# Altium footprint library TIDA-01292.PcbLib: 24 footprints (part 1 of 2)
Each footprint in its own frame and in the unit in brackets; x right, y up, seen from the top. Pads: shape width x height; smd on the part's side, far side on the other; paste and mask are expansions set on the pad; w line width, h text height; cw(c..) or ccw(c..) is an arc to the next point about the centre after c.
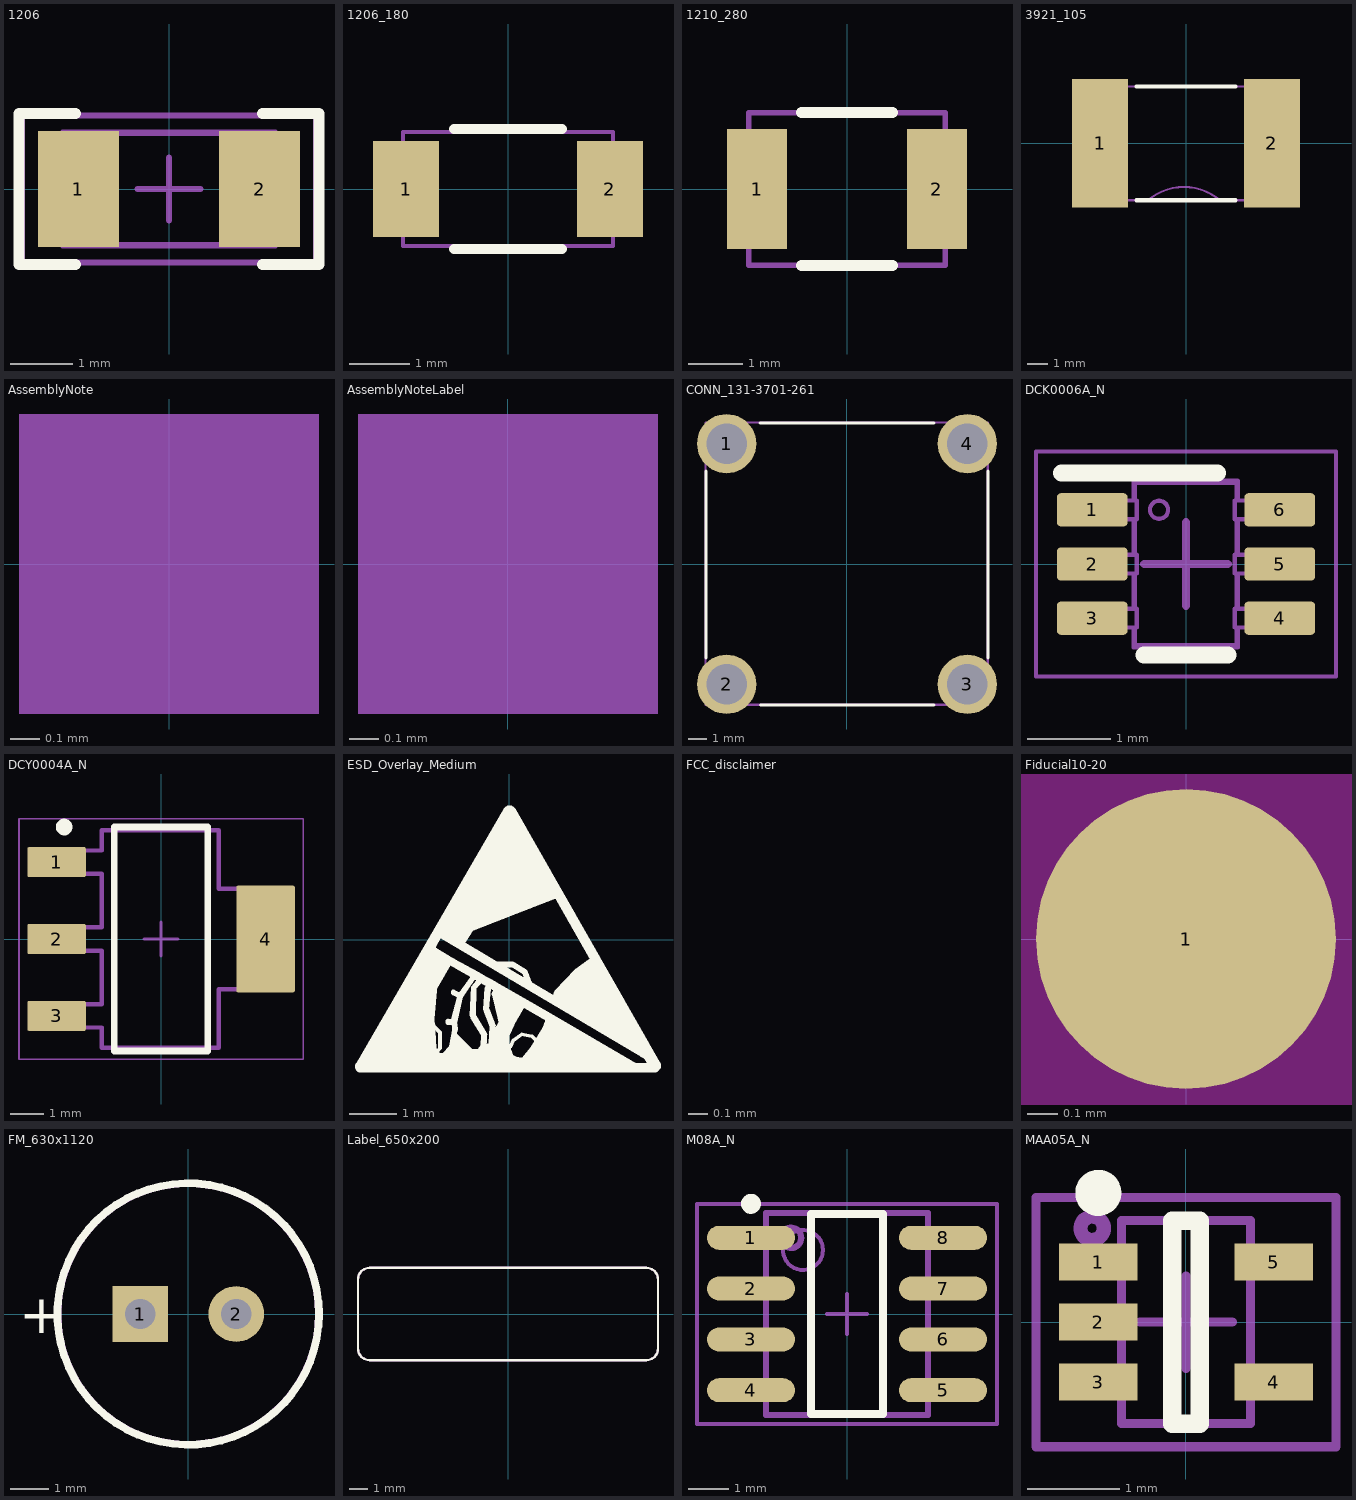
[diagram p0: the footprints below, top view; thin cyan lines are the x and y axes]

## 1206 [mm] "1206 from SM-752 data"
height 1.35
pads (2):
  rect 1.3x1.85 smd: 1(-1.45,0) 2(1.45,0)
Top Overlay:
  lines w0.178: -1.5,-1.21 -2.4,-1.21 -2.4,1.21 -1.5,1.21 ; 1.5,-1.21 2.4,-1.21 2.4,1.21 1.5,1.21
Mechanical 5:
  lines w0.1: -1.7,-0.9 -1.7,0.9 1.7,0.9 1.7,-0.9 -1.7,-0.9
  text ".Designator" at -1.475,-0.4 h0.89
Mechanical 13:
  lines w0.1: -1.2,-0.9 -1.2,0.9 ; 1.2,-0.9 1.2,0.9 ; -1.7,-0.9 -1.7,0.9 1.7,0.9 1.7,-0.9 -1.7,-0.9
Mechanical 15:
  lines w0.1: -0.5,0 0.5,0 ; 0,-0.5 0,0.5 ; -2.35,-1.175 -2.35,1.175 2.35,1.175 2.35,-1.175 -2.35,-1.175
3D body: height 1.35, standoff 0, extent 1.201,-0.899 1.699,0.899
3D body: height 1.35, standoff 0, extent -1.199,-0.899 1.199,0.899
3D body: height 1.35, standoff 0, extent -1.699,-0.899 -1.201,0.899

## 1206_180 [mm] "1206_180"
height 1.8
pads (2):
  rect 1.1x1.6 smd: 1(-1.7,0) 2(1.7,0)
Top Overlay:
  lines w0.17: -0.9,-1 0.9,-1 ; -0.9,1 0.9,1
Mechanical 5:
  lines w0.07: -1.75,-0.95 1.75,-0.95 1.75,0.95 -1.75,0.95 -1.75,-0.95
  text ".Designator" at 1.143,0.432 h0.89
3D body: height 1.8, standoff 0, extent -1.241,-0.949 -0.793,0.949
3D body: height 1.8, standoff 0, extent -1.299,-0.949 1.299,0.949
3D body: height 1.8, standoff 0, extent 1.301,-0.949 1.749,0.949

## 1210_280 [mm] "SMD, 2-Leads, Body 3.6x2.8mm, Height 2.8mm"
height 2.8
pads (2):
  rect 1.1x2.2 smd: 1(-1.65,0) 2(1.65,0)
Top Overlay:
  lines w0.2: -0.835,-1.4 0.835,-1.4 ; -0.835,1.4 0.835,1.4
Mechanical 5:
  lines w0.1: -1.8,-1.4 -1.8,1.4 1.8,1.4 1.8,-1.4 -1.8,-1.4
  text ".Designator" at 0.483,-1.028 h0.89
3D body: height 2.8, standoff 0, extent -1.8,-1.4 -1.6,1.4
3D body: height 2.8, standoff 0, extent -1.6,-1.4 1.6,1.4
3D body: height 2.8, standoff 0, extent 1.6,-1.4 1.8,1.4

## 3921_105 [mm] "SMD, 2-Leads, Body 10x5.2mm"
height 1.05
pads (2):
  rect 2.7x6.2 smd: 1(-4.15,0) 2(4.15,0)
Top Overlay:
  lines w0.2: -2.4,-2.75 2.4,-2.75 ; -2.4,2.75 2.4,2.75
Mechanical 5:
  lines w0.1: -5.15,-2.75 -1.85,-2.75 cw(c-0.1,-4.809) 1.65,-2.75 5.15,-2.75 5.15,2.75 -5.15,2.75 -5.15,-2.75
  text ".Designator" at -0.467,0.98 h0.89
3D body: height 1.05, standoff 0, extent -5.15,-2.75 5.15,2.75

## AssemblyNote [mm] "Assembly Note"
Mechanical 5:
  rectangle: -0.508,-0.508 0.508,0.508
  text ".Designator" at -4.191,-0.508 h0.89
  text ".Comment" at 1.143,-0.508 h0.89

## AssemblyNoteLabel [mm] "Assembly Note for PCB Labels"
Mechanical 5:
  rectangle: -0.508,-0.508 0.508,0.508
  text ".Designator" at -4.191,-0.508 h0.89
  text "Install label in silkscreened box after final wash.  Text shall be 8 pt font.  Text shall be per the Label Table in the PDF schematic." at 1.143,-0.508 h0.89

## CONN_131-3701-261 [mm]
pads (4):
  round 3.2 hole 2.2 mask+0.051: 1(-6.5,6.5) 2(-6.5,-6.5) 3(6.5,-6.5) 4(6.5,6.5)
Top Overlay:
  lines w0.17: -7.62,-5.08 -7.62,5.025 ; -4.699,7.62 4.699,7.62 ; -4.674,-7.62 4.699,-7.62 ; 7.62,-5.08 7.62,5.029
Mechanical 5:
  lines w0.127: -7.643,7.643 -6.729,7.643 -6.729,6.729 -7.643,6.729 -7.643,7.643 ; -7.643,7.643 7.597,7.643 7.597,-7.597 -7.643,-7.597 -7.643,7.643
  text ".Designator" at -1.055,0.227 h0.89

## DCK0006A_N [mm] "SOT23, 6-Leads, Body 2x1.3mm, Pitch 0.65mm, Lead Span 2.1mm, IPC Medium Density"
height 1.1
pads (6):
  rrect25% 0.85x0.4 smd: 1(-1.125,0.65) 2(-1.125,0) 3(-1.125,-0.65) 4(1.125,-0.65) 5(1.125,0) 6(1.125,0.65)
Top Overlay:
  lines w0.2: -1.499,1.092 0.381,1.092 ; -0.508,-1.092 0.508,-1.092
Mechanical 5:
  lines w0.05: -0.613,-0.763 -0.613,-0.976 0.607,-0.976 0.607,-0.763 ; -0.613,-0.538 -0.613,-0.113 ; -0.613,0.112 -0.613,0.537 ; -0.613,0.762 -0.613,0.974 0.607,0.974 0.607,0.762 ; 0.607,-0.538 0.607,-0.113 ; 0.607,0.112 0.607,0.537 ; -0.628,-0.763 -0.628,-1.001 0.622,-1.001 0.622,-0.763 ; -0.628,-0.763 -0.853,-0.763 -0.865,-0.763 -0.959,-0.763 -1.143,-0.763 -1.143,-0.538 -0.959,-0.538 -0.865,-0.538 -0.853,-0.538 -0.628,-0.538 ; -0.628,-0.763 -0.591,-0.763 -0.591,-0.538 -0.628,-0.538 ; -0.628,-0.538 -0.628,-0.113 ; -0.628,-0.113 -0.853,-0.113 -0.865,-0.113 -0.959,-0.113 -1.143,-0.113 -1.143,0.112 -0.959,0.112 -0.865,0.112 -0.853,0.112 -0.628,0.112 ; -0.628,-0.113 -0.591,-0.113 -0.591,0.112 -0.628,0.112 ; -0.628,0.112 -0.628,0.537 ; -0.628,0.537 -0.853,0.537 -0.865,0.537 -0.959,0.537 -1.143,0.537 -1.143,0.762 -0.959,0.762 -0.865,0.762 -0.853,0.762 -0.628,0.762 ; -0.628,0.537 -0.591,0.537 -0.591,0.762 -0.628,0.762 ; -0.628,0.762 -0.628,0.999 0.622,0.999 0.622,0.762 ; 0.622,-0.763 0.847,-0.763 0.859,-0.763 0.953,-0.763 1.137,-0.763 1.137,-0.538 0.953,-0.538 0.859,-0.538 0.847,-0.538 0.622,-0.538 ; 0.622,-0.763 0.585,-0.763 0.585,-0.538 0.622,-0.538 ; 0.622,-0.538 0.622,-0.113 ; 0.622,-0.113 0.585,-0.113 0.585,0.112 0.622,0.112 ; 0.622,-0.113 0.847,-0.113 0.859,-0.113 0.953,-0.113 1.137,-0.113 1.137,0.112 0.953,0.112 0.859,0.112 0.847,0.112 0.622,0.112 ; 0.622,0.112 0.622,0.537 ; 0.622,0.537 0.847,0.537 0.859,0.537 0.953,0.537 1.137,0.537 1.137,0.762 0.953,0.762 0.859,0.762 0.847,0.762 0.622,0.762 ; 0.622,0.537 0.585,0.537 0.585,0.762 0.622,0.762 ; -0.432,0.65 cw(c-0.323,0.65) -0.215,0.65 cw(c-0.323,0.65) -0.432,0.65
  text ".Designator" at 0.751,2.27 h0.89
Mechanical 15:
  lines w0.05: -1.8,-1.35 -1.8,1.35 1.8,1.35 1.8,-1.35 -1.8,-1.35
  lines w0.1: -0.5,0 0.5,0 ; 0,-0.5 0,0.5
3D body: height 0.95, standoff 0, extent -1.14,-1 1.14,1

## DCY0004A_N [mm] "SOT223/SC73, 4-Leads, Body 6.5x3.5mm, Pitch 2.3mm, Lead Span 7mm, IPC Medium Density"
height 1.8
pads (4):
  rrect11% 1.75x0.9 smd: 1(-3.125,2.3) 2(-3.125,0) 3(-3.125,-2.3)
  rrect6% 1.75x3.2 smd: 4(3.125,0)
Top Overlay:
  circle w0.25: c-2.9,3.35 r0.125
  lines w0.2: -1.4,-3.35 -1.4,3.35 1.4,3.35 1.4,-3.35 -1.4,-3.35
Mechanical 5:
  lines w0.127: -3.525,-2.65 -3.525,-1.95 -2.797,-1.95 -2.612,-1.95 -2.374,-1.95 -2.003,-1.95 -1.775,-1.95 -1.775,-0.35 -2.003,-0.35 -2.374,-0.35 -2.612,-0.35 -2.797,-0.35 -3.525,-0.35 -3.525,0.35 -2.797,0.35 -2.612,0.35 -2.374,0.35 -2.003,0.35 -1.775,0.35 -1.775,1.95 -2.003,1.95 -2.374,1.95 -2.612,1.95 -2.797,1.95 -3.525,1.95 -3.525,2.65 -2.797,2.65 -2.612,2.65 -2.374,2.65 -2.003,2.65 -1.775,2.65 -1.775,3.25 1.725,3.25 1.725,1.5 1.953,1.5 2.324,1.5 2.562,1.5 2.747,1.5 3.475,1.5 3.475,-1.5 2.747,-1.5 2.562,-1.5 2.324,-1.5 1.953,-1.5 1.725,-1.5 1.725,-3.25 -1.775,-3.25 -1.775,-2.65 -2.003,-2.65 -2.374,-2.65 -2.612,-2.65 -2.797,-2.65 -3.525,-2.65
  text ".Designator" at 0.754,0.432 h0.89
Mechanical 15:
  lines w0.05: -4.25,-3.6 4.25,-3.6 4.25,3.6 -4.25,3.6 -4.25,-3.6
  lines w0.1: -0.5,0 0.5,0 ; 0,-0.5 0,0.5
3D body: height 1.68, standoff 0, extent -3.48,-3.25 3.48,3.25

## ESD_Overlay_Medium [mm]
height 18
Top Overlay:
  drawing of 6916 lines, arcs and shapes, not listed

## FCC_disclaimer [mm]
height 8.64
Top Overlay:
  text "For evaluation only; not FCC approved for resale." at 90.373,65.405 h1.52

## Fiducial10-20 [mm]
pads (1):
  round 1 smd mask+0.5: 1(0,0)
Top Layer keep-out:
  circle w1.178: c0,0 r0.5

## FM_630x1120 [mm] "PANASONIC"
height 12.7
pads (2):
  rect 1.45x1.45 hole 0.787: 1(-1.25,0)
  round 1.45 hole 0.787: 2(1.25,0)
Top Overlay:
  circle w0.2: c0,0 r3.401
  text "+" at -4.4,-0.5 h1.02
Mechanical 5:
  circle w0.1: c0,0 r3.35
  text ".Designator" at 0.635,0.762 h0.89
  text "+" at -4.4,-0.5 h0.89
3D body: height 12.71, standoff -4, extent -3.373,-3.394 3.397,3.395

## Label_650x200 [mm] "Thermal Transfer Label"
height 0.025
Top Overlay:
  lines w0.127: -8.255,-1.905 ccw(c-7.62,-1.905) -7.62,-2.54 7.62,-2.54 ccw(c7.62,-1.905) 8.255,-1.905 8.255,1.905 ccw(c7.62,1.905) 7.62,2.54 -7.62,2.54 ccw(c-7.62,1.905) -8.255,1.905 -8.255,-1.905
Mechanical 5:
  lines w0.127: -8.255,-1.905 ccw(c-7.62,-1.905) -7.62,-2.54 7.62,-2.54 ccw(c7.62,-1.905) 8.255,-1.905 8.255,1.905 ccw(c7.62,1.905) 7.62,2.54 -7.62,2.54 ccw(c-7.62,1.905) -8.255,1.905 -8.255,-1.905
  text ".Designator" at -1.524,-0.508 h0.89
3D body: height 0.03, standoff 0, extent -8.268,-2.553 8.268,2.553

## M08A_N [mm] "SOIC, 8-Leads, Body 4.9x3.9mm, Pitch 1.27mm, IPC Medium Density"
height 1.75
pads (8):
  oval 2.2x0.6 smd: 1(-2.4,1.905) 2(-2.4,0.635) 3(-2.4,-0.635) 4(-2.4,-1.905) 5(2.4,-1.905) 6(2.4,-0.635) 7(2.4,0.635) 8(2.4,1.905)
Top Overlay:
  circle w0.25: c-2.4,2.755 r0.125
  lines w0.2: -0.9,-2.5 -0.9,2.5 0.9,2.5 0.9,-2.5 -0.9,-2.5
Mechanical 5:
  circle w0.152: c-1.397,1.905 r0.254
  lines w0.127: -2.032,-2.54 2.032,-2.54 2.032,2.54 -2.032,2.54 -2.032,-2.54
  text ".Designator" at -0.635,-0.635 h0.89
Mechanical 13:
  circle w0.1: c-1.1,1.6 r0.5
  lines w0.1: -2,-2.5 -2,2.5 2,2.5 2,-2.5 -2,-2.5
Mechanical 15:
  lines w0.1: -0.5,0 0.5,0 ; 0,-0.5 0,0.5 ; -3.75,-2.75 -3.75,2.75 3.75,2.75 3.75,-2.75 -3.75,-2.75
3D body: height 1.75, standoff 0, extent -2,-2.5 2,2.5

## MAA05A_N [mm] "SOT353, 5-Leads, Body 2x1.3mm, Pitch 0.65mm, Lead Span 2.1mm, IPC Medium Density"
height 1.1
pads (5):
  rect 0.85x0.4 smd: 1(-0.95,0.65) 2(-0.95,0) 3(-0.95,-0.65) 4(0.95,-0.65) 5(0.95,0.65)
Top Overlay:
  circle w0.25: c-0.95,1.4 r0.125
  lines w0.2: -0.15,-1.1 -0.15,1.1 0.15,1.1 0.15,-1.1 -0.15,-1.1
Mechanical 5:
  circle w0.152: c-1.016,1.016 r0.127
  lines w0.1: -0.7,-1.1 -0.7,1.1 0.7,1.1 0.7,-1.1 -0.7,-1.1
  text ".Designator" at -0.677,1.44 h0.89
Mechanical 15:
  lines w0.1: -0.5,0 0.5,0 ; 0,-0.5 0,0.5 ; -1.625,-1.35 -1.625,1.35 1.625,1.35 1.625,-1.35 -1.625,-1.35
3D body: height 1.1, standoff 0, extent -0.7,-1.1 0.7,1.1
